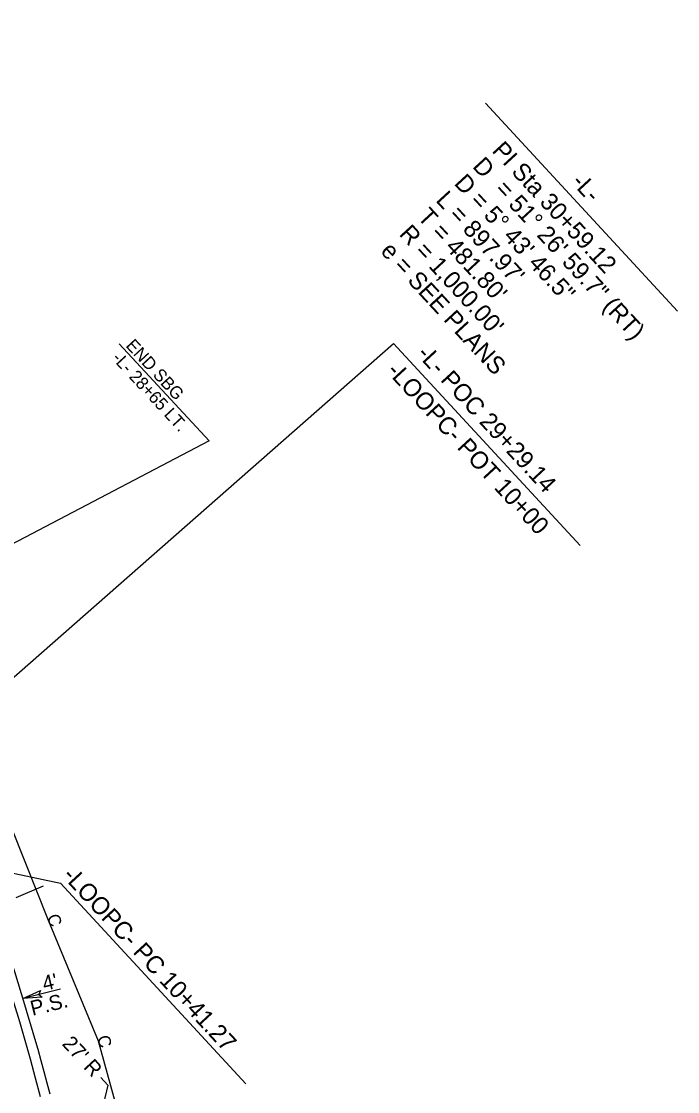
# Model space of a CAD drawing. Extents: x 1702862 to 1704514, y 793768 to 796215.
# Drawn here: x 1703965.8 to 1704228.7, y 794386.1 to 794815.1 of the extents above; entities that cross this region are included whole.
import ezdxf

# ---------------------------------------------------------------- set-up
doc = ezdxf.new("R2010")
doc.units = 0
for name, color, linetype in [('Default', 7, 'Continuous'), ('Prop Dimension', 7, 'Continuous'), ('Prop Dimension Text', 7, 'Continuous'), ('Prop EOT', 7, 'Continuous'), ('Prop Horizontal Alignment', 7, 'Continuous'), ('Prop Horizontal Alignment Curve and Spiral Data', 7, 'Continuous'), ('Prop Horizontal Alignment Station Label', 7, 'Continuous'), ('Prop Lane Lines', 7, 'Continuous'), ('Prop Leader Line Medium', 7, 'Continuous'), ('Prop Paved Shoulder', 7, 'Continuous'), ('Prop SS Cut Line', 7, 'Continuous'), ('Prop SS Misc', 7, 'Continuous'), ('Prop SS Transition Line', 7, 'Continuous'), ('Prop Terminator CELL', 7, 'Continuous')]:
    doc.layers.add(name, color=color, linetype=linetype)

msp = doc.modelspace()

# ---------------------------------------------------------------- linework, layer by layer
at = {"layer": 'Prop Dimension'}
msp.add_line((1703981.48, 794427.14), (1703966.46, 794423.44), dxfattribs=at)
at = {"layer": 'Prop Dimension Text'}
msp.add_lwpolyline([(1703997.7, 794391.74), (1704000.49, 794388.71), (1703994.76, 794364.3)], dxfattribs=at)
at = {"layer": 'Prop EOT'}
msp.add_line((1703963.67, 794463.92), (1703974.65, 794468.55), dxfattribs=at)
msp.add_arc((1702989.11, 794124.65), 1018, 14.75888, 42.70907, dxfattribs=at)
at = {"layer": 'Prop Horizontal Alignment'}
msp.add_arc((1702989.11, 794124.65), 1000, 351.25916, 42.70907, dxfattribs=at)
at = {"layer": 'Prop Horizontal Alignment Curve and Spiral Data'}
msp.add_line((1704151.77, 794782.38), (1704228.7, 794699.03), dxfattribs=at)
at = {"layer": 'Prop Horizontal Alignment Station Label'}
for p, q in [((1703912.65, 794508.14), (1704114.85, 794686.06)), ((1704114.85, 794686.06), (1704189.68, 794604.99)), ((1703874.55, 794492.27), (1703981.5, 794469.6))]:
    msp.add_line(p, q, dxfattribs=at)
msp.add_lwpolyline([(1703981.5, 794469.6), (1704055.74, 794389.17)], dxfattribs=at)
at = {"layer": 'Prop Lane Lines'}
for radius, start in [(1006, 0.00687), (994, 359.40932), (980, 359.40932)]:
    msp.add_arc((1702989.11, 794124.65), radius, start, 42.70907, dxfattribs=at)
at = {"layer": 'Prop Leader Line Medium'}
for q in [(1704004.97, 794685.82), (1703909.49, 794578.04)]:
    msp.add_line((1704040.99, 794646.92), q, dxfattribs=at)
at = {"layer": 'Prop Paved Shoulder'}
msp.add_arc((1702989.11, 794124.65), 1022, 14.75888, 18.93305, dxfattribs=at)
at = {"layer": 'Prop SS Cut Line'}
for p, q in [((1703976.48, 794454.84), (1703996.51, 794406.41)), ((1703996.51, 794406.41), (1704006.42, 794370.71))]:
    msp.add_line(p, q, dxfattribs=at)
at = {"layer": 'Prop SS Transition Line'}
msp.add_line((1703957.17, 794503.16), (1703976.48, 794454.84), dxfattribs=at)
at = {"layer": 'Prop Terminator CELL'}
msp.add_lwpolyline([(1703974.08, 794423.96), (1703966.34, 794423.41), (1703973.48, 794426.57), (1703972.86, 794425.01)], close=True, dxfattribs=at)

# ---------------------------------------------------------------- texts
at = {"layer": 'Default'}
for s, p in [('END SBG', (1704007.35, 794684.94)), ('-L- 28+65 LT.', (1704001.84, 794679.86))]:
    msp.add_text(s, height=5, rotation=312.7091, dxfattribs=at).set_placement(p)
at = {"layer": 'Prop Dimension Text'}
for s, rotation, p in [("4'", 13.8336, (1703975.02, 794426.41)), ('P.S.', 13.8336, (1703970.23, 794416.44)), ("27' R", 312.7091, (1703981.78, 794405.02))]:
    msp.add_text(s, height=6, rotation=rotation, dxfattribs=at).set_placement(p)
at = {"layer": 'Prop Horizontal Alignment Curve and Spiral Data'}
for s, p in [('PI Sta 30+59.12', (1704154.01, 794763.05)), ('D', (1704146.21, 794756.76)), ('D = 5%%d 43\' 46.5"', (1704138.86, 794749.98)), ('= 51%%d 26\' 59.7" (RT)', (1704155.14, 794747.52)), ('-L-', (1704185.8, 794750.44)), ("L = 897.97'", (1704131.51, 794743.2)), ("T = 481.80'", (1704124.16, 794736.42)), ("R = 1,000.00'", (1704116.82, 794729.63)), ('e = SEE PLANS', (1704109.37, 794722.73))]:
    msp.add_text(s, height=7, rotation=312.7091, dxfattribs=at).set_placement(p)
at = {"layer": 'Prop Horizontal Alignment Station Label'}
for s, rotation, p in [('-L- POC 29+29.14', 312.7091, (1704123.86, 794681.53)), ('-LOOPC- POT 10+00', 312.7091, (1704111.8, 794674.7)), ('-LOOPC- PC 10+41.27', 312.7636, (1703981.91, 794472.38))]:
    msp.add_text(s, height=7, rotation=rotation, dxfattribs=at).set_placement(p)
at = {"layer": 'Prop SS Misc'}
for rotation, p in [(288.4908, (1703975.99, 794456.3)), (285.626, (1703996.09, 794407.89))]:
    msp.add_text('C', height=5, rotation=rotation, dxfattribs=at).set_placement(p)

doc.saveas('drawing.dxf')
